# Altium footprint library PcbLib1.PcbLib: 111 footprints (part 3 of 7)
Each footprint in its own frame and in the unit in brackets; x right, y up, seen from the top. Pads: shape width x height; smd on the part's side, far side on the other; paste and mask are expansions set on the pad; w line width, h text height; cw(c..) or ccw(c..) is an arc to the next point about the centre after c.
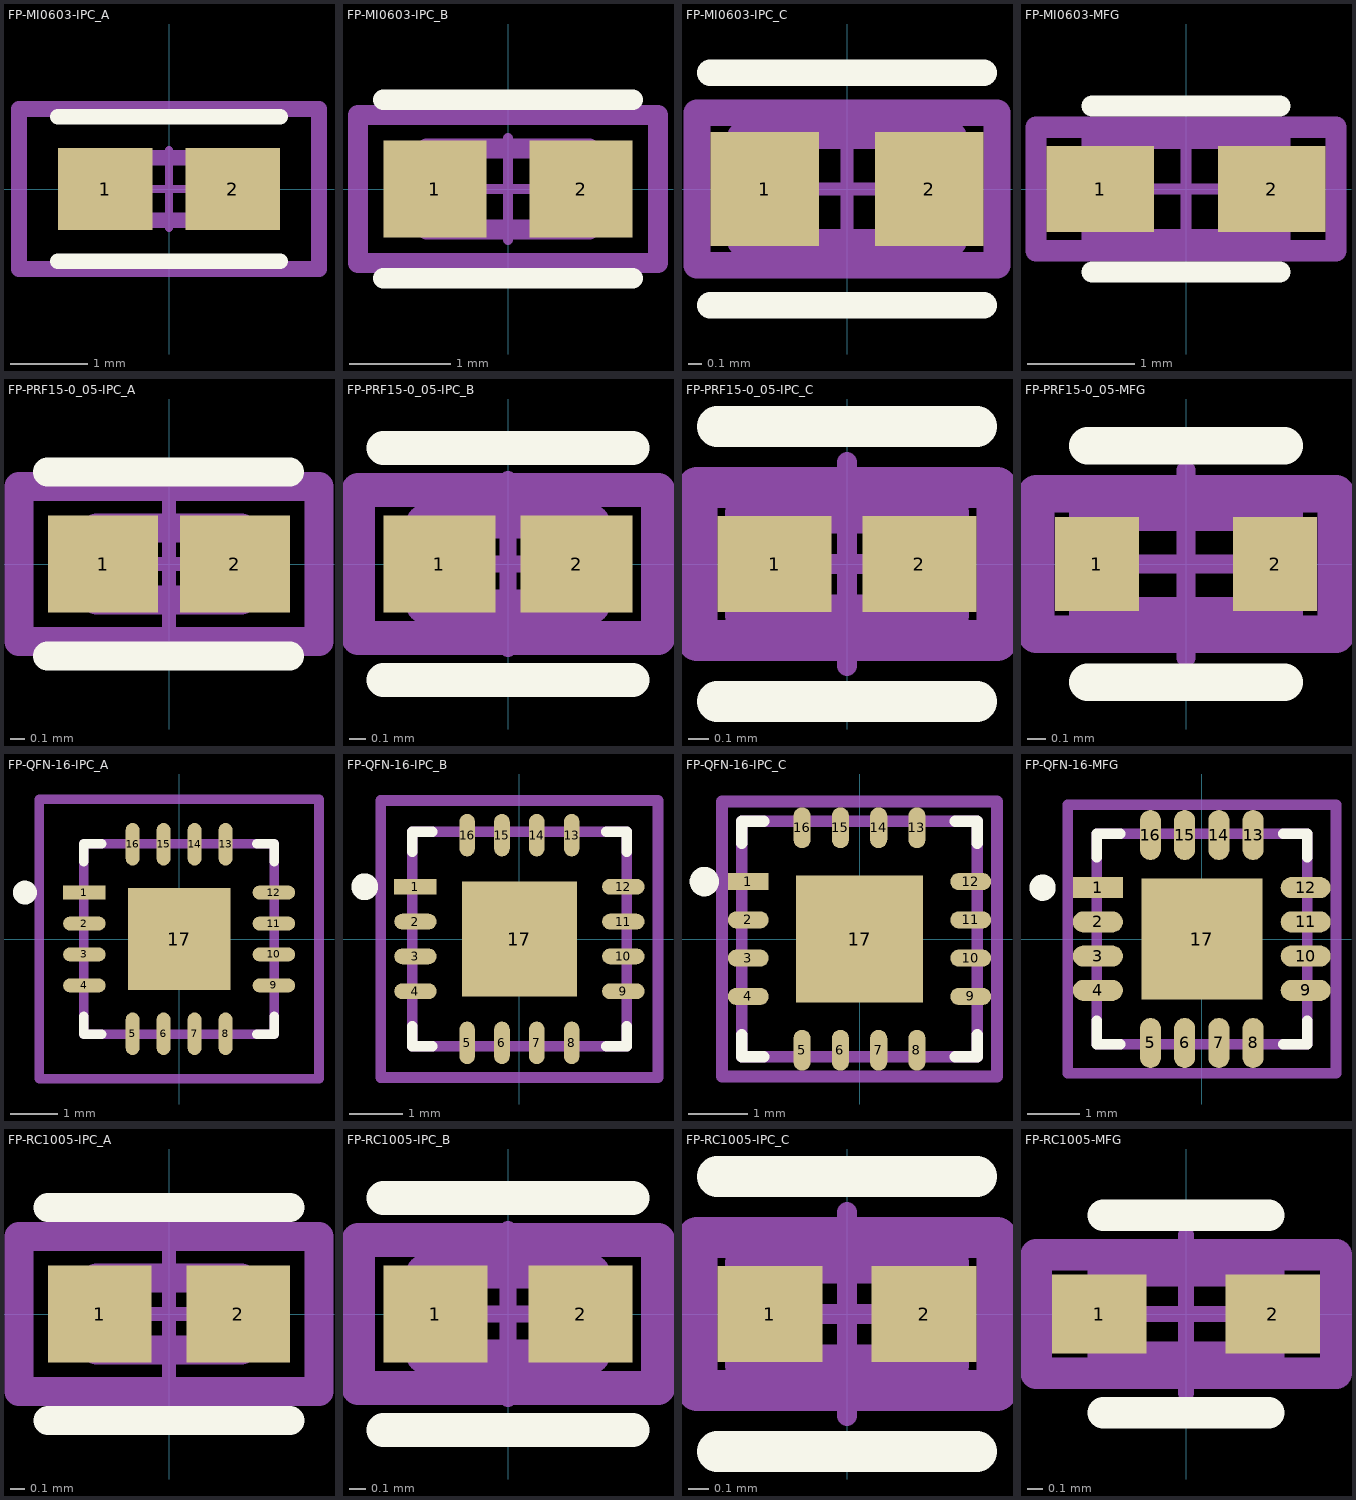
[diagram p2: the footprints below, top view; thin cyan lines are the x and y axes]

## FP-MI0603-IPC_A [mm]
pads (2):
  rect 1.217x1.058 smd paste+0 mask+0: 1(-0.821,0) 2(0.821,0)
Top Overlay:
  lines w0.2: -1.429,-0.929 1.429,-0.929 ; -1.429,0.929 1.429,0.929
Mechanical 5:
  lines w0.2: -1.929,-1.029 1.929,-1.029 1.929,1.029 -1.929,1.029 -1.929,-1.029
  text ".Designator" at 0,0.188 h1
Mechanical 13:
  lines w0.2: -0.8,-0.4 0.8,-0.4 0.8,0.4 -0.8,0.4 -0.8,-0.4
Mechanical 15:
  lines w0.2: -1.929,-1.029 1.929,-1.029 1.929,1.029 -1.929,1.029 -1.929,-1.029
Mechanical 16:
  lines w0.1: -0.5,0 0.5,0 ; 0,-0.5 0,0.5
3D body "FBead_Laird_MI0603J601R-10_eec.STEP": height 0.25, standoff 0, extent -1.929,-1.029 1.929,1.029

## FP-MI0603-IPC_B [mm]
pads (2):
  rect 1.017x0.958 smd paste+0 mask+0: 1(-0.721,0) 2(0.721,0)
Top Overlay:
  lines w0.2: -1.229,-0.879 1.229,-0.879 ; -1.229,0.879 1.229,0.879
Mechanical 5:
  lines w0.2: -1.479,-0.729 -1.479,0.729 1.479,0.729 1.479,-0.729 -1.479,-0.729
  text ".Designator" at 0,0.188 h1
Mechanical 13:
  lines w0.2: -0.8,-0.4 -0.8,0.4 0.8,0.4 0.8,-0.4 -0.8,-0.4
Mechanical 15:
  lines w0.2: -1.479,-0.729 -1.479,0.729 1.479,0.729 1.479,-0.729 -1.479,-0.729
Mechanical 16:
  lines w0.1: -0.5,0 0.5,0 ; 0,-0.5 0,0.5
3D body "FBead_Laird_MI0603J601R-10_eec.STEP": height 0.25, standoff 0, extent -1.479,-0.729 1.479,0.729

## FP-MI0603-IPC_C [mm]
pads (2):
  rect 0.817x0.858 smd paste+0 mask+0: 1(-0.621,0) 2(0.621,0)
Top Overlay:
  lines w0.2: -1.029,-0.875 1.029,-0.875 ; -1.029,0.875 1.029,0.875
Mechanical 5:
  lines w0.2: -1.129,-0.575 1.129,-0.575 1.129,0.575 -1.129,0.575 -1.129,-0.575
  text ".Designator" at 0,0.188 h1
Mechanical 13:
  lines w0.2: -0.8,-0.4 0.8,-0.4 0.8,0.4 -0.8,0.4 -0.8,-0.4
Mechanical 15:
  lines w0.2: -1.129,-0.575 1.129,-0.575 1.129,0.575 -1.129,0.575 -1.129,-0.575
Mechanical 16:
  lines w0.1: -0.5,0 0.5,0 ; 0,-0.5 0,0.5
3D body "FBead_Laird_MI0603J601R-10_eec.STEP": height 0.25, standoff 0, extent -1.129,-0.575 1.129,0.575

## FP-MI0603-MFG [mm]
pads (2):
  rect 1x0.8 smd paste+0 mask+0: 1(-0.8,0) 2(0.8,0)
Top Overlay:
  lines w0.2: -0.875,-0.775 0.875,-0.775 ; -0.875,0.775 0.875,0.775
Mechanical 5:
  lines w0.2: -1.4,-0.575 1.4,-0.575 1.4,0.575 -1.4,0.575 -1.4,-0.575
  text ".Designator" at 0,0.188 h1
Mechanical 13:
  lines w0.2: -0.875,-0.475 0.875,-0.475 0.875,0.475 -0.875,0.475 -0.875,-0.475
Mechanical 15:
  lines w0.2: -1.4,-0.575 1.4,-0.575 1.4,0.575 -1.4,0.575 -1.4,-0.575
Mechanical 16:
  lines w0.1: -0.5,0 0.5,0 ; 0,-0.5 0,0.5
3D body "FBead_Laird_MI0603J601R-10_eec.STEP": height 0.25, standoff 0, extent -1.4,-0.575 1.4,0.575

## FP-PRF15-0_05-IPC_A [mm]
pads (2):
  rect 0.761x0.672 smd paste+0 mask+0: 1(-0.456,0) 2(0.456,0)
Top Overlay:
  lines w0.2: -0.838,-0.635 0.834,-0.635 ; -0.838,0.635 0.834,0.635
Mechanical 5:
  lines w0.2: -1.036,-0.536 -1.036,0.536 1.036,0.536 1.036,-0.536 -1.036,-0.536
  text ".Designator" at 0,-0.001 h1
Mechanical 13:
  lines w0.2: -0.5,-0.25 -0.5,0.25 0.5,0.25 0.5,-0.25 -0.5,-0.25
Mechanical 15:
  lines w0.2: -1.036,-0.536 -1.036,0.536 1.036,0.536 1.036,-0.536 -1.036,-0.536
Mechanical 16:
  lines w0.1: -0.5,0 0.5,0 -0.5,0 ; 0,-0.5 0,0.5 0,-0.5
3D body "_Murata_PRF15BE103RB6RC_eec.STEP": height 0.25, standoff 0, extent -1.036,-0.536 1.036,0.536

## FP-PRF15-0_05-IPC_B [mm]
pads (2):
  rect 0.661x0.572 smd paste+0 mask+0: 1(-0.406,0) 2(0.406,0)
Top Overlay:
  lines w0.2: -0.736,-0.686 0.736,-0.686 ; -0.736,0.686 0.736,0.686
Mechanical 5:
  lines w0.2: -0.886,-0.436 0.886,-0.436 0.886,0.436 -0.886,0.436 -0.886,-0.436
  text ".Designator" at 0,-0.001 h1
Mechanical 13:
  lines w0.2: -0.5,-0.25 0.5,-0.25 0.5,0.25 -0.5,0.25 -0.5,-0.25
Mechanical 15:
  lines w0.2: -0.886,-0.436 0.886,-0.436 0.886,0.436 -0.886,0.436 -0.886,-0.436
Mechanical 16:
  lines w0.1: -0.5,0 0.5,0 -0.5,0 ; 0,-0.5 0,0.5 0,-0.5
3D body "_Murata_PRF15BE103RB6RC_eec.STEP": height 0.25, standoff 0, extent -0.886,-0.436 0.886,0.436

## FP-PRF15-0_05-IPC_C [mil]
pads (2):
  rect 22.1x18.6 smd paste+0 mask+0: 1(-14,0) 2(14,0)
Top Overlay:
  lines w7.87: -25.05,-26.57 25.05,-26.57 ; -25.05,26.57 25.05,26.57
Mechanical 5:
  lines w7.87: -28.99,-14.76 28.99,-14.76 28.99,14.76 -28.99,14.76 -28.99,-14.76
  text ".Designator" at 0,-0.02 h39.37
Mechanical 13:
  lines w7.87: -19.68,-9.84 19.68,-9.84 19.68,9.84 -19.68,9.84 -19.68,-9.84
Mechanical 15:
  lines w7.87: -28.99,-14.76 28.99,-14.76 28.99,14.76 -28.99,14.76 -28.99,-14.76
Mechanical 16:
  lines w3.94: -19.68,0 19.68,0 -19.68,0 ; 0,-19.68 0,19.68 0,-19.68
3D body "_Murata_PRF15BE103RB6RC_eec.STEP": height 10, standoff 0, extent -28.99,-14.76 28.99,14.76

## FP-PRF15-0_05-MFG [mm]
pads (2):
  rect 0.45x0.5 smd paste+0 mask+0: 1(-0.475,0) 2(0.475,0)
Top Overlay:
  lines w0.2: -0.525,-0.63 0.525,-0.63 ; -0.525,0.63 0.525,0.63
Mechanical 5:
  lines w0.2: -0.8,-0.375 -0.8,0.375 0.8,0.375 0.8,-0.375 -0.8,-0.375
  text ".Designator" at 0,0.188 h1
Mechanical 13:
  lines w0.2: -0.525,-0.275 -0.525,0.275 0.525,0.275 0.525,-0.275 -0.525,-0.275
Mechanical 15:
  lines w0.2: -0.8,-0.375 -0.8,0.375 0.8,0.375 0.8,-0.375 -0.8,-0.375
Mechanical 16:
  lines w0.1: -0.5,0 0.5,0 ; 0,-0.5 0,0.5
3D body "_Murata_PRF15BE103RB6RC_eec.STEP": height 0.25, standoff 0, extent -0.8,-0.375 0.8,0.375

## FP-QFN-16-IPC_A [mm]
pads (17):
  rect 0.894x0.292 smd paste+0 mask+0: 1(-1.989,0.975)
  rrect100% 0.894x0.292 smd paste+0 mask+0: 2(-1.989,0.325) 3(-1.989,-0.325) 4(-1.989,-0.975) 9(1.989,-0.975) 10(1.989,-0.325) 11(1.989,0.325) 12(1.989,0.975)
  rrect100% 0.292x0.894 smd paste+0 mask+0: 5(-0.975,-1.989) 6(-0.325,-1.989) 7(0.325,-1.989) 8(0.975,-1.989) 13(0.975,1.989) 14(0.325,1.989) 15(-0.325,1.989) 16(-0.975,1.989)
  rect 2.15x2.15 smd: 17(0,0)
Top Overlay:
  circle w0.25: c-3.235,0.975 r0.125
  lines w0.2: -2,-1.625 -2,-2 -1.625,-2 ; -2,1.625 -2,2 -1.625,2 ; 1.625,-2 2,-2 2,-1.625 ; 1.625,2 2,2 2,1.625
Top Paste:
  rectangle: -0.68,-0.68 0.68,0.68
Mechanical 5:
  lines w0.2: -2.935,-2.935 2.935,-2.935 2.935,2.935 -2.935,2.935 -2.935,-2.935
  text ".Designator" at -2.921,-3.876 h1
Mechanical 13:
  lines w0.2: -2,-2 2,-2 2,2 -2,2 -2,-2
Mechanical 15:
  lines w0.2: -2.935,-2.935 2.935,-2.935 2.935,2.935 -2.935,2.935 -2.935,-2.935
Mechanical 16:
  lines w0.1: -0.5,0 0.5,0 ; 0,-0.5 0,0.5
3D body "IC_FTDI_FT230XQ-R_eec.STEP": height 0.8, standoff 0, extent -2.001,-2.001 2.001,2.001

## FP-QFN-16-IPC_B [mm]
pads (17):
  rect 0.794x0.292 smd paste+0 mask+0: 1(-1.939,0.975)
  rrect100% 0.794x0.292 smd paste+0 mask+0: 2(-1.939,0.325) 3(-1.939,-0.325) 4(-1.939,-0.975) 9(1.939,-0.975) 10(1.939,-0.325) 11(1.939,0.325) 12(1.939,0.975)
  rrect100% 0.292x0.794 smd paste+0 mask+0: 5(-0.975,-1.939) 6(-0.325,-1.939) 7(0.325,-1.939) 8(0.975,-1.939) 13(0.975,1.939) 14(0.325,1.939) 15(-0.325,1.939) 16(-0.975,1.939)
  rect 2.15x2.15 smd paste-1000 mask+0: 17(0,0)
Top Overlay:
  circle w0.25: c-2.885,0.975 r0.125
  lines w0.2: -2,-1.625 -2,-2 -1.625,-2 ; -2,1.625 -2,2 -1.625,2 ; 1.625,-2 2,-2 2,-1.625 ; 1.625,2 2,2 2,1.625
Top Paste:
  rectangle: -0.68,-0.68 0.68,0.68
Mechanical 5:
  lines w0.2: -2.585,-2.585 2.585,-2.585 2.585,2.585 -2.585,2.585 -2.585,-2.585
  text ".Designator" at 0,0.188 h1
Mechanical 13:
  lines w0.2: -2,-2 2,-2 2,2 -2,2 -2,-2
Mechanical 15:
  lines w0.2: -2.585,-2.585 2.585,-2.585 2.585,2.585 -2.585,2.585 -2.585,-2.585
Mechanical 16:
  lines w0.1: -0.5,0 0.5,0 ; 0,-0.5 0,0.5
3D body "IC_FTDI_FT230XQ-R_eec.STEP": height 0.25, standoff 0, extent -2.585,-2.585 2.585,2.585

## FP-QFN-16-IPC_C [mm]
pads (17):
  rect 0.694x0.292 smd paste+0 mask+0: 1(-1.889,0.975)
  rrect100% 0.694x0.292 smd paste+0 mask+0: 2(-1.889,0.325) 3(-1.889,-0.325) 4(-1.889,-0.975) 9(1.889,-0.975) 10(1.889,-0.325) 11(1.889,0.325) 12(1.889,0.975)
  rrect100% 0.292x0.694 smd paste+0 mask+0: 5(-0.975,-1.889) 6(-0.325,-1.889) 7(0.325,-1.889) 8(0.975,-1.889) 13(0.975,1.889) 14(0.325,1.889) 15(-0.325,1.889) 16(-0.975,1.889)
  rect 2.15x2.15 smd paste-1000 mask+0: 17(0,0)
Top Overlay:
  circle w0.25: c-2.635,0.975 r0.125
  lines w0.2: -2,-1.625 -2,-2 -1.625,-2 ; -2,1.625 -2,2 -1.625,2 ; 1.625,-2 2,-2 2,-1.625 ; 1.625,2 2,2 2,1.625
Top Paste:
  rectangle: -0.68,-0.68 0.68,0.68
Mechanical 5:
  lines w0.2: -2.335,-2.335 2.335,-2.335 2.335,2.335 -2.335,2.335 -2.335,-2.335
  text ".Designator" at 0,0.188 h1
Mechanical 13:
  lines w0.2: -2,-2 2,-2 2,2 -2,2 -2,-2
Mechanical 15:
  lines w0.2: -2.335,-2.335 2.335,-2.335 2.335,2.335 -2.335,2.335 -2.335,-2.335
Mechanical 16:
  lines w0.1: -0.5,0 0.5,0 ; 0,-0.5 0,0.5
3D body "IC_FTDI_FT230XQ-R_eec.STEP": height 0.25, standoff 0, extent -2.335,-2.335 2.335,2.335

## FP-QFN-16-MFG [mm]
pads (17):
  rect 0.95x0.4 smd paste+0 mask+0: 1(-1.975,0.975)
  rrect100% 0.95x0.4 smd paste+0 mask+0: 2(-1.975,0.325) 3(-1.975,-0.325) 4(-1.975,-0.975) 9(1.975,-0.975) 10(1.975,-0.325) 11(1.975,0.325) 12(1.975,0.975)
  rrect100% 0.4x0.95 smd paste+0 mask+0: 5(-0.975,-1.975) 6(-0.325,-1.975) 7(0.325,-1.975) 8(0.975,-1.975) 13(0.975,1.975) 14(0.325,1.975) 15(-0.325,1.975) 16(-0.975,1.975)
  rect 2.3x2.3 smd paste+0 mask+0: 17(0,0)
Top Overlay:
  circle w0.25: c-3.025,0.975 r0.125
  lines w0.2: -2,-1.55 -2,-2 -1.55,-2 ; -2,1.55 -2,2 -1.55,2 ; 1.55,-2 2,-2 2,-1.55 ; 1.55,2 2,2 2,1.55
Mechanical 5:
  lines w0.2: -2.55,-2.55 -2.55,2.55 2.55,2.55 2.55,-2.55 -2.55,-2.55
  text ".Designator" at 0,0.188 h1
Mechanical 13:
  lines w0.2: -2,-2 -2,2 2,2 2,-2 -2,-2
Mechanical 15:
  lines w0.2: -2.55,-2.55 -2.55,2.55 2.55,2.55 2.55,-2.55 -2.55,-2.55
Mechanical 16:
  lines w0.1: -0.5,0 0.5,0 ; 0,-0.5 0,0.5
3D body "IC_FTDI_FT230XQ-R_eec.STEP": height 0.25, standoff 0, extent -2.55,-2.55 2.55,2.55

## FP-RC1005-IPC_A [mm]
pads (2):
  rect 0.715x0.672 smd paste+0 mask+0: 1(-0.479,0) 2(0.479,0)
Top Overlay:
  lines w0.2: -0.836,-0.736 0.836,-0.736 ; -0.836,0.736 0.836,0.736
Mechanical 5:
  lines w0.2: -1.036,-0.536 -1.036,0.536 1.036,0.536 1.036,-0.536 -1.036,-0.536
  text ".Designator" at 0,0.188 h1
Mechanical 13:
  lines w0.2: -0.5,-0.25 -0.5,0.25 0.5,0.25 0.5,-0.25 -0.5,-0.25
Mechanical 15:
  lines w0.2: -1.036,-0.536 -1.036,0.536 1.036,0.536 1.036,-0.536 -1.036,-0.536
Mechanical 16:
  lines w0.1: -0.5,0 0.5,0 ; 0,-0.5 0,0.5
3D body "Res_Samsung_RC1005F2944CS_eec.STEP": height 0.25, standoff 0, extent -1.036,-0.536 1.036,0.536

## FP-RC1005-IPC_B [mm]
pads (2):
  rect 0.615x0.572 smd paste+0 mask+0: 1(-0.429,0) 2(0.429,0)
Top Overlay:
  lines w0.2: -0.736,-0.686 0.736,-0.686 ; -0.736,0.686 0.736,0.686
Mechanical 5:
  lines w0.2: -0.886,-0.436 0.886,-0.436 0.886,0.436 -0.886,0.436 -0.886,-0.436
  text ".Designator" at 0,0.188 h1
Mechanical 13:
  lines w0.2: -0.5,-0.25 0.5,-0.25 0.5,0.25 -0.5,0.25 -0.5,-0.25
Mechanical 15:
  lines w0.2: -0.886,-0.436 0.886,-0.436 0.886,0.436 -0.886,0.436 -0.886,-0.436
Mechanical 16:
  lines w0.1: -0.5,0 0.5,0 ; 0,-0.5 0,0.5
3D body "Res_Samsung_RC1005F2944CS_eec.STEP": height 0.25, standoff 0, extent -0.886,-0.436 0.886,0.436

## FP-RC1005-IPC_C [mm]
pads (2):
  rect 0.515x0.472 smd paste+0 mask+0: 1(-0.379,0) 2(0.379,0)
Top Overlay:
  lines w0.2: -0.636,-0.675 0.636,-0.675 ; -0.636,0.675 0.636,0.675
Mechanical 5:
  lines w0.2: -0.736,-0.375 0.736,-0.375 0.736,0.375 -0.736,0.375 -0.736,-0.375
  text ".Designator" at 0,0.188 h1
Mechanical 13:
  lines w0.2: -0.5,-0.25 0.5,-0.25 0.5,0.25 -0.5,0.25 -0.5,-0.25
Mechanical 15:
  lines w0.2: -0.736,-0.375 0.736,-0.375 0.736,0.375 -0.736,0.375 -0.736,-0.375
Mechanical 16:
  lines w0.1: -0.5,0 0.5,0 ; 0,-0.5 0,0.5
3D body "Res_Samsung_RC1005F2944CS_eec.STEP": height 0.25, standoff 0, extent -0.736,-0.375 0.736,0.375

## FP-RC1005-MFG [mm]
pads (2):
  rect 0.6x0.5 smd paste+0 mask+0: 1(-0.55,0) 2(0.55,0)
Top Overlay:
  lines w0.2: -0.525,-0.625 0.525,-0.625 ; -0.525,0.625 0.525,0.625
Mechanical 5:
  lines w0.2: -0.95,-0.375 -0.95,0.375 0.95,0.375 0.95,-0.375 -0.95,-0.375
  text ".Designator" at 0,0.188 h1
Mechanical 13:
  lines w0.2: -0.525,-0.275 -0.525,0.275 0.525,0.275 0.525,-0.275 -0.525,-0.275
Mechanical 15:
  lines w0.2: -0.95,-0.375 -0.95,0.375 0.95,0.375 0.95,-0.375 -0.95,-0.375
Mechanical 16:
  lines w0.1: -0.5,0 0.5,0 ; 0,-0.5 0,0.5
3D body "Res_Samsung_RC1005F2944CS_eec.STEP": height 0.25, standoff 0, extent -0.95,-0.375 0.95,0.375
